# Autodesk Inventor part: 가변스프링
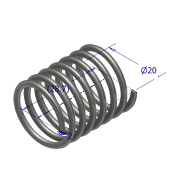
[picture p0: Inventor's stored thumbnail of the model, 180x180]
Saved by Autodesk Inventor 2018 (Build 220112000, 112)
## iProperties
Created: 2020-01
Part Number: 가변스프링
Material: 스테인레스 스틸
Document SubType Name: Modeling
Designer: Administrator
Density: 8 g/cm^3
Appearance: 반연마
Mass: 10.8861 g
Surface Area: 27.5659 cm^2
Volume: 1.36077 cm^3
Author: Administrator
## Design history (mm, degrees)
sketch "스케치1"
  geometry: L1 (0, 0)-(10, 0); L2 (10, 0)-(10, 28.7); L3 (10, 28.7)-(0, 28.7); L4 (0, 28.7)-(0, 0); C1 r 1 at (10, 0)
  constraints: 8 end point, 2 parallel, 1 centre point, 1 coincident, 1 horizontal, 1 perpendicular
  dimensions: "d0" = 2 diameter of C1; "d1" = 28.7 distance of L3.end L1.start (derived); "d2" = 20 diameter of L2 L4
feature "코일1" sketch "스케치1" pitch "d3" = 10; turns "d5" = 7; dims "d4" = 28.7 (= d1), "d6" = 0, angle "d7" = 90 deg, angle "d8" = 90 deg, "d9" = 0, "d10" = 0
sketch "스케치2"
  geometry: L1 (-9, 0)-(-11, 0) reference; 1 further point
  constraints: 1 horizontal alignment
extrude "돌출1" cut sketch "스케치2" extent not by distance; stored distance "d11" = 10; taper "d12" = 0 deg
node "작업 평면1"
sketch "스케치3"
  geometry: L1 (-1, 0)-(1, 0) reference; 1 further point
  constraints: 1 horizontal alignment
extrude "돌출2" cut sketch "스케치3" extent not by distance; stored distance "d14" = 10; taper "d15" = 0 deg
node "솔리드1"
node "절단 모서리 투영1"
node "절단 모서리 투영2"
other parameters: "d13" = 90 deg
